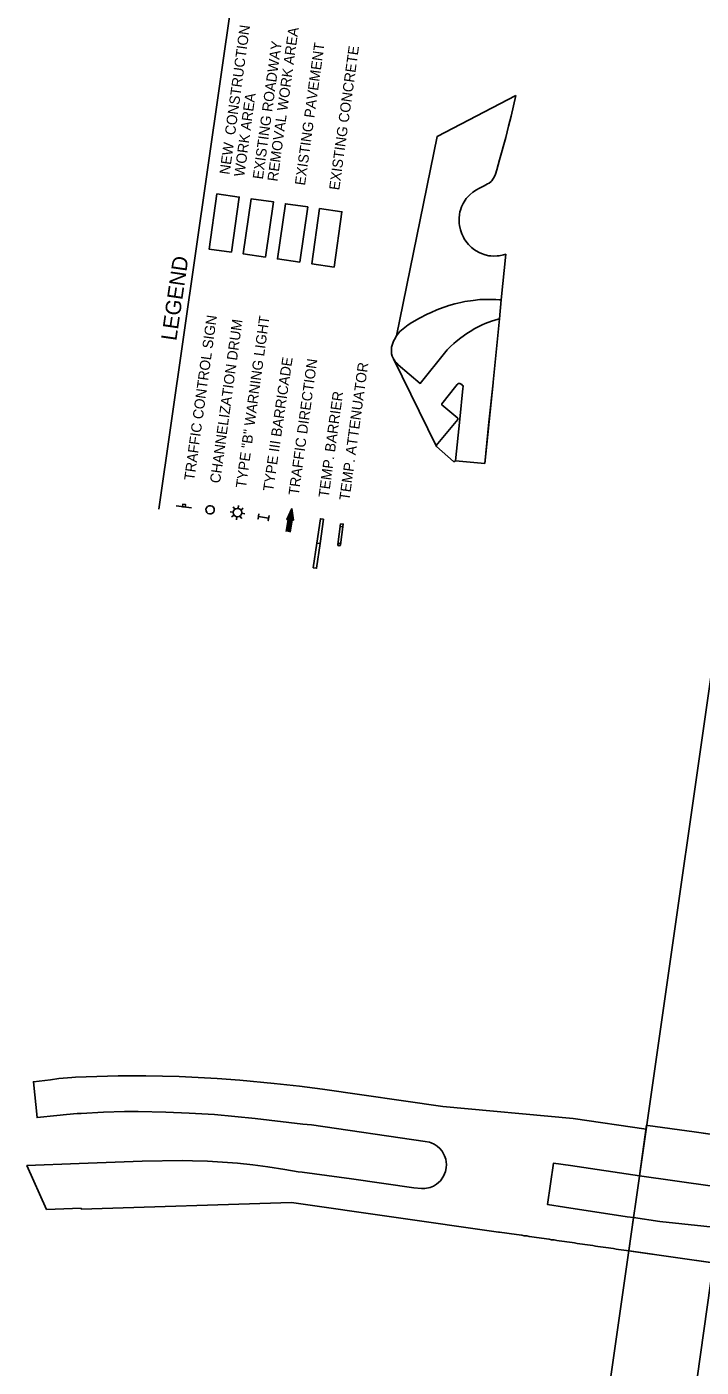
# Model space of a CAD drawing. Extents: x 1795987 to 1799700, y 243690 to 251545.
# Drawn here: x 1797401 to 1797911, y 248808 to 249823 of the extents above; entities that cross this region are included whole.
import ezdxf

# ---------------------------------------------------------------- set-up
doc = ezdxf.new("R2010")
doc.units = 0
for name, color, linetype in [('EP', 7, 'Continuous'), ('LEGEND', 7, 'Continuous'), ('Level 23', 7, 'Continuous'), ('Level 62', 7, 'Continuous')]:
    doc.layers.add(name, color=color, linetype=linetype)

# ---------------------------------------------------------------- blocks, each defined once
blk = doc.blocks.new('T21LR')
at = {"layer": 'Level 23'}
for p, q in [((0, 2), (31.5, 2)), ((0, -2), (31.5, -2))]:
    blk.add_line(p, q, dxfattribs=at)
blk.add_lwpolyline([(0, -2), (4, -2), (4, 2), (0, 2)], close=True, dxfattribs=at)
blk.add_circle((31.5, 0), 2, dxfattribs=at)

msp = doc.modelspace()

# ---------------------------------------------------------------- linework, layer by layer
at = {"layer": 'EP'}
for points in [[(1797729.6, 249614.5), (1797725.1, 249613.4), (1797720.6, 249612.2), (1797718.4, 249611.5), (1797716.1, 249610.7), (1797711.5, 249608.9), (1797707.1, 249606.9), (1797704.1, 249605.5), (1797698.2, 249602.5), (1797692.5, 249599.3), (1797689.7, 249597.6), (1797687.1, 249595.6), (1797685.8, 249594.6), (1797683.5, 249592.4), (1797682.4, 249591.2), (1797680.9, 249589.2), (1797679.3, 249586.5), (1797678.6, 249585.1), (1797677.8, 249582.8), (1797677.2, 249580.6), (1797677.1, 249579.4), (1797677, 249577.7), (1797677.1, 249576.9), (1797677.2, 249575.6), (1797677.7, 249573.7), (1797678.5, 249571.9), (1797679, 249571), (1797680.2, 249569.3), (1797681, 249568.5), (1797682.2, 249567.3), (1797698.9, 249553.1), (1797718.2, 249577.4), (1797719.3, 249578.7), (1797721.7, 249581.2), (1797724.2, 249583.5)], [(1797727.3, 249526.8), (1797715.3, 249536.9), (1797715.1, 249537.8), (1797725.7, 249551.1), (1797726.8, 249552.4), (1797727.3, 249552.8), (1797727.9, 249553), (1797728.2, 249553), (1797728.9, 249553), (1797729.9, 249552.6), (1797730.3, 249552.3), (1797730.9, 249551.7), (1797731, 249551.5), (1797731.2, 249550.8), (1797731.1, 249549.3), (1797728.7, 249526), (1797725.5, 249494.5), (1797724.7, 249494.1), (1797723.9, 249494.1), (1797711.1, 249505.4), (1797711, 249506.2), (1797727.4, 249525.8), (1797727.3, 249526.8)], [(1797950.4, 249280.9), (1797956.6, 249327.5), (1797918.9, 249332.5), (1797841.7, 248792.1)], [(1797841.7, 248792.1), (1797905.8, 248781.8), (1797956.6, 249142)]]:
    msp.add_lwpolyline(points, dxfattribs=at)
at = {"layer": 'LEGEND'}
for p, q in [((1797501.1, 249457.9), (1797556.6, 249845.4)), ((1797525.7, 249458.9), (1797514.1, 249460.5)), ((1797557.3, 249455.7), (1797555.1, 249456)), ((1797556.1, 249452), (1797558, 249453.3)), ((1797558.6, 249457.8), (1797557.2, 249459.7)), ((1797561, 249458.4), (1797561.3, 249460.7)), ((1797563.8, 249450.9), (1797562.4, 249452.7)), ((1797564.9, 249458.6), (1797563.1, 249457.2)), ((1797563.7, 249454.8), (1797566, 249454.5)), ((1797601.6, 249458.4), (1797597.8, 249450.2)), ((1797602.8, 249449.5), (1797601.6, 249458.4)), ((1797560.1, 249452.1), (1797559.7, 249449.8)), ((1797598.8, 249450.1), (1797597.3, 249441.1)), ((1797597.8, 249450.2), (1797598.8, 249450.1)), ((1797600.4, 249440.6), (1797601.8, 249449.6)), ((1797601.8, 249449.6), (1797602.8, 249449.5))]:
    msp.add_line(p, q, dxfattribs=at)
for points in [[(1797555.9, 249652.5), (1797561.9, 249694.3), (1797545, 249696.7), (1797539, 249654.9)], [(1797581.8, 249648.8), (1797587.8, 249690.6), (1797570.9, 249693), (1797564.9, 249651.2)], [(1797607.7, 249645), (1797613.7, 249686.9), (1797596.8, 249689.3), (1797590.8, 249647.5)], [(1797633.6, 249641.3), (1797639.6, 249683.2), (1797622.7, 249685.6), (1797616.7, 249643.8)], [(1797518.9, 249459.8), (1797519.2, 249461.8), (1797521.1, 249461.5), (1797520.8, 249459.5)], [(1797625.7, 249450.4), (1797623.3, 249450.7), (1797620.6, 249432.1), (1797623.1, 249431.8)], [(1797623.1, 249431.8), (1797620.6, 249432.1), (1797617.9, 249413.6), (1797620.4, 249413.2)]]:
    msp.add_lwpolyline(points, close=True, dxfattribs=at)
for points in [[(1797584.5, 249453.1), (1797583.8, 249449.2), (1797584.1, 249451.2), (1797576.4, 249452.4), (1797576.1, 249450.5), (1797576.8, 249454.3)], [(1797599.5, 249453.9), (1797597.5, 249441.1)], [(1797599.9, 249454.7), (1797597.8, 249441.1)], [(1797600.3, 249455.5), (1797598, 249441)], [(1797600.7, 249456.4), (1797598.3, 249441)], [(1797601.1, 249457.2), (1797598.5, 249440.9)], [(1797599.1, 249453), (1797598.7, 249450.1)], [(1797601.5, 249458.1), (1797598.8, 249440.9)], [(1797601.7, 249457.8), (1797599, 249440.9)], [(1797601.8, 249456.9), (1797599.3, 249440.8)], [(1797601.9, 249456), (1797599.6, 249440.8)], [(1797602.1, 249455), (1797599.8, 249440.7)], [(1797602.2, 249454.1), (1797600.1, 249440.7)], [(1797602.3, 249453.2), (1797600.3, 249440.7)], [(1797597.9, 249450.5), (1797597.9, 249450.2)], [(1797598.3, 249451.3), (1797598.1, 249450.2)], [(1797598.7, 249452.2), (1797598.4, 249450.2)], [(1797602.4, 249452.3), (1797602, 249449.6)], [(1797602.5, 249451.3), (1797602.3, 249449.6)], [(1797602.7, 249450.4), (1797602.5, 249449.5)]]:
    msp.add_lwpolyline(points, dxfattribs=at)
msp.add_circle((1797560.5, 249455.3), 3.19, dxfattribs=at)
for start, end in [(81.8439, 261.8439), (261.8439, 81.8439)]:
    msp.add_arc((1797539.8, 249457.4), 3.18, start, end, dxfattribs=at)
at = {"layer": 'Level 62'}
for p, q in [((1797771.3, 249771.3), (1797711.7, 249740.2)), ((1797711.7, 249740.2), (1797680.9, 249589.2)), ((1797760.1, 249616.4), (1797763.5, 249651)), ((1797758.7, 249602), (1797760.1, 249616.4)), ((1797754.1, 249554), (1797758.7, 249602)), ((1797678.5, 249571.9), (1797711.1, 249505.4)), ((1797747.6, 249492.6), (1797754.1, 249553.6)), ((1797754.1, 249553.6), (1797754.1, 249554)), ((1797725.5, 249494.5), (1797747.6, 249492.6))]:
    msp.add_line(p, q, dxfattribs=at)
for points in [[(1797771.3, 249771.3), (1797711.7, 249740.2), (1797680.9, 249589.2), (1797682.4, 249591.2), (1797683.5, 249592.4), (1797685.8, 249594.6), (1797687.1, 249595.6), (1797689.7, 249597.6), (1797692.5, 249599.3), (1797698.2, 249602.5), (1797704.1, 249605.5), (1797707.1, 249606.9), (1797711.5, 249608.9), (1797716.1, 249610.7), (1797718.4, 249611.5), (1797720.6, 249612.2), (1797725.1, 249613.4), (1797729.6, 249614.5), (1797732.7, 249615.1), (1797738.8, 249616), (1797743.9, 249616.6), (1797746.4, 249616.7), (1797750.2, 249616.8), (1797754.1, 249616.7), (1797756, 249616.6), (1797758.7, 249616.4), (1797760.1, 249616.4), (1797763.5, 249651), (1797761.9, 249650.5), (1797758.6, 249649.9), (1797757, 249649.7), (1797754.5, 249649.6), (1797752.3, 249649.7), (1797750.8, 249649.9), (1797747.9, 249650.6), (1797745.2, 249651.5), (1797743.4, 249652.3), (1797741.1, 249653.6), (1797740, 249654.3), (1797737.6, 249656.1), (1797736.6, 249657.1), (1797735.4, 249658.3), (1797733.4, 249660.8), (1797732.2, 249662.6), (1797731.5, 249663.9), (1797730.3, 249666.5), (1797729.2, 249669.5), (1797728.5, 249672.7), (1797728.3, 249674.3), (1797728.2, 249676.7), (1797728.2, 249678.2), (1797728.5, 249681.2), (1797728.9, 249683.1), (1797729.3, 249684.4), (1797730.1, 249686.9), (1797731.3, 249689.5), (1797732.9, 249692), (1797733.7, 249693.2), (1797735.1, 249694.8), (1797736.3, 249696), (1797738.7, 249698), (1797741.4, 249699.8), (1797743.3, 249700.9), (1797747.2, 249702.9), (1797749.7, 249704.2), (1797751, 249704.9), (1797752.4, 249706.1), (1797753, 249706.7), (1797753.9, 249707.8), (1797754.4, 249708.5), (1797755.1, 249710), (1797755.7, 249711.6), (1797756.7, 249714.9), (1797758.9, 249722.6), (1797763.5, 249739.5), (1797765.7, 249747.9), (1797767.7, 249755.7), (1797771.3, 249771.3)], [(1797763.5, 249651), (1797761.9, 249650.5), (1797758.6, 249649.9), (1797757, 249649.7), (1797754.5, 249649.6), (1797752.3, 249649.7), (1797750.8, 249649.9), (1797747.9, 249650.6), (1797745.2, 249651.5), (1797743.4, 249652.3), (1797741.1, 249653.6), (1797740, 249654.3), (1797737.6, 249656.1), (1797736.6, 249657.1), (1797735.4, 249658.3), (1797733.4, 249660.8), (1797732.2, 249662.6), (1797731.5, 249663.9), (1797730.3, 249666.5), (1797729.2, 249669.5), (1797728.5, 249672.7), (1797728.3, 249674.3), (1797728.2, 249676.7), (1797728.2, 249678.2), (1797728.5, 249681.2), (1797728.9, 249683.1), (1797729.3, 249684.4), (1797730.1, 249686.9), (1797731.3, 249689.5), (1797732.9, 249692), (1797733.7, 249693.2), (1797735.1, 249694.8), (1797736.3, 249696), (1797738.7, 249698), (1797741.4, 249699.8), (1797743.3, 249700.9), (1797747.2, 249702.9), (1797749.7, 249704.2), (1797751, 249704.9), (1797752.4, 249706.1), (1797753, 249706.7), (1797753.9, 249707.8), (1797754.4, 249708.5), (1797755.1, 249710), (1797755.7, 249711.6), (1797756.7, 249714.9), (1797758.9, 249722.6), (1797763.5, 249739.5), (1797765.7, 249747.9), (1797767.7, 249755.7), (1797771.3, 249771.3)], [(1797590.8, 249647.5), (1797607.7, 249645), (1797613.7, 249686.9), (1797596.8, 249689.3), (1797590.8, 249647.5)], [(1797760.1, 249616.4), (1797758.7, 249616.4), (1797756, 249616.6), (1797754.1, 249616.7), (1797750.2, 249616.8), (1797746.4, 249616.7), (1797743.9, 249616.6), (1797738.8, 249616), (1797732.7, 249615.1), (1797729.6, 249614.5), (1797725.1, 249613.4), (1797720.6, 249612.2), (1797718.4, 249611.5), (1797716.1, 249610.7), (1797711.5, 249608.9), (1797707.1, 249606.9), (1797704.1, 249605.5), (1797698.2, 249602.5), (1797692.5, 249599.3), (1797689.7, 249597.6), (1797687.1, 249595.6), (1797685.8, 249594.6), (1797683.5, 249592.4), (1797682.4, 249591.2), (1797680.9, 249589.2)], [(1797758.7, 249602), (1797757.7, 249601.8), (1797752.7, 249600.3), (1797747.9, 249598.5), (1797745.6, 249597.5), (1797743.7, 249596.6), (1797740.1, 249594.7), (1797736.5, 249592.5), (1797734.2, 249591), (1797729.6, 249587.8), (1797726, 249585), (1797724.2, 249583.5), (1797721.7, 249581.2), (1797719.3, 249578.7), (1797718.2, 249577.4), (1797698.9, 249553.1), (1797682.2, 249567.3), (1797681, 249568.5), (1797680.2, 249569.3), (1797679, 249571), (1797678.5, 249571.9)], [(1797727.3, 249526.8), (1797715.3, 249536.9), (1797715.1, 249537.8), (1797725.7, 249551.1), (1797726.8, 249552.4), (1797727.3, 249552.8), (1797727.9, 249553), (1797728.2, 249553), (1797728.9, 249553), (1797729.9, 249552.6), (1797730.3, 249552.3), (1797730.9, 249551.7), (1797731, 249551.5), (1797731.2, 249550.8), (1797731.1, 249549.3), (1797728.7, 249526), (1797725.5, 249494.5)], [(1797747.6, 249492.6), (1797750.8, 249523.7), (1797754.1, 249553.6)], [(1797711.1, 249505.4), (1797711, 249506.2), (1797727.4, 249525.8), (1797727.3, 249526.8)], [(1797442.3, 248928.4), (1797442.3, 248927.8), (1797601.3, 248932.8), (1797758, 248910.4), (1797758.8, 248910.3), (1797760.6, 248910.1), (1797762.5, 248909.8), (1797764.3, 248909.5), (1797766.2, 248909.3), (1797768, 248909), (1797769.9, 248908.7), (1797771.8, 248908.5), (1797773.7, 248908.2), (1797775.6, 248907.9), (1797777.5, 248907.6), (1797779.4, 248907.4), (1797781.3, 248907.1), (1797783.2, 248906.8), (1797785.1, 248906.6), (1797786.9, 248906.3), (1797788.8, 248906), (1797790.7, 248905.7), (1797792.6, 248905.5), (1797794.5, 248905.2), (1797796.4, 248904.9), (1797798.3, 248904.6), (1797800.2, 248904.4), (1797802.1, 248904.1), (1797804, 248903.8), (1797805.9, 248903.5), (1797807.9, 248903.2), (1797809.8, 248903), (1797811.8, 248902.7), (1797813.7, 248902.4), (1797815.7, 248902.1), (1797817.7, 248901.8), (1797819.6, 248901.5), (1797821.6, 248901.2), (1797823.5, 248901), (1797825.5, 248900.7), (1797827.4, 248900.4), (1797829.4, 248900.1), (1797831.4, 248899.8), (1797833.3, 248899.5), (1797835.3, 248899.2), (1797837.2, 248899), (1797839.2, 248898.7), (1797841.2, 248898.4), (1797843.1, 248898.1), (1797845.1, 248897.8), (1797847, 248897.5), (1797849, 248897.2), (1797850.9, 248897), (1797852.9, 248896.7), (1797854.9, 248896.4), (1797856.6, 248896.1), (1797860.2, 248921.3), (1797855.5, 248922), (1797808, 248929.2), (1797795.2, 248931.2), (1797799.8, 248962.6), (1797812.5, 248960.7), (1797864.7, 248953), (1797869.7, 248988.3), (1797814.6, 248996.3), (1797716, 249005.4), (1797624.8, 249018.5), (1797607.5, 249020.8), (1797588.4, 249023), (1797562.3, 249025.4), (1797545.1, 249026.7), (1797516.4, 249028.1), (1797491.2, 249028.6), (1797470.2, 249028.6), (1797438, 249027.7), (1797435.2, 249027.5), (1797425.4, 249026.6), (1797418.9, 249025.8), (1797406.1, 249024.2), (1797408.8, 248997.1), (1797423.7, 248998.7), (1797431.2, 248999.4), (1797439.2, 249000.1), (1797442.3, 249000.3), (1797459.1, 249001.2), (1797474.9, 249001.6), (1797485.4, 249001.7), (1797506.4, 249001.3), (1797523.9, 249000.5), (1797543.2, 248999.3), (1797573.8, 248996.5), (1797609.9, 248992.2), (1797616.5, 248991.6), (1797702.5, 248979), (1797705.8, 248978.4), (1797707.1, 248978), (1797709.5, 248976.9), (1797711.7, 248975.4), (1797713.7, 248973.7), (1797715.4, 248971.6), (1797717.3, 248968.1), (1797718.2, 248965.6), (1797718.7, 248961.6), (1797718.5, 248959), (1797718, 248956.3), (1797716.4, 248952.6), (1797714.1, 248949.3), (1797711.1, 248946.6), (1797708.8, 248945.2), (1797706.3, 248944.2), (1797702.4, 248943.4), (1797699.7, 248943.3), (1797694.1, 248944), (1797646.8, 248950.7), (1797609.4, 248955.7), (1797606.5, 248955.9), (1797596.3, 248957.7), (1797583.6, 248959.8), (1797572.1, 248961.3), (1797560.6, 248962.5), (1797549.2, 248963.4), (1797537.9, 248964), (1797526.6, 248964.4), (1797519, 248964.5), (1797488.4, 248964.1), (1797440.8, 248962.3), (1797401.1, 248960.7), (1797416.1, 248927.5), (1797442.3, 248928.4)], [(1797864.7, 248953), (1797870.2, 248991.3), (1797871.2, 248991.1), (1797906.1, 248986.4), (1797934.1, 248982.3)], [(1797939, 248981.6), (1797906.1, 248986.4), (1797871.2, 248991.1)], [(1797975.3, 248937.3), (1797864.7, 248953)], [(1797994.6, 248906.7), (1797992, 248906.6), (1797880.1, 248918.3), (1797860.2, 248921.3), (1797856.6, 248896.1), (1797856.8, 248896.1), (1797858.3, 248895.9), (1797858.8, 248895.8), (1797858.8, 248895.8), (1797892.1, 248891.1), (1797920.6, 248887)], [(1797858.3, 248895.9), (1797892.1, 248891.1), (1797925.5, 248886.3)]]:
    msp.add_lwpolyline(points, dxfattribs=at)

# ---------------------------------------------------------------- block references
at = {"layer": 'LEGEND', "xscale": 0.5000000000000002, "yscale": 0.5000000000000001, "rotation": -98.00678026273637}
msp.add_blockref('T21LR', (1797639.6, 249446.7), dxfattribs=at)

# ---------------------------------------------------------------- texts
at = {"layer": 'LEGEND'}
for s, height, rotation, p in [('NEW  CONSTRUCTION', 7.8, 82.1569, (1797554.5, 249711)), ('REMOVAL WORK AREA', 7.8, 82.1569, (1797590.8, 249705.8)), ('EXISTING ROADWAY', 7.8, 82.1569, (1797579.7, 249707.4)), ('EXISTING PAVEMENT', 7.8, 82.1569, (1797611.6, 249702.8)), ('EXISTING CONCRETE', 7.8, 82.1569, (1797637.5, 249699.2)), ('WORK AREA', 7.8, 82.1569, (1797565.6, 249709.4)), ('LEGEND', 11.7, 81.6779, (1797514.2, 249585)), ('TRAFFIC CONTROL SIGN', 7.8, 82.1569, (1797527.8, 249479.2)), ('CHANNELIZATION DRUM', 7.8, 82.1569, (1797547.3, 249477.2)), ('TYPE "B" WARNING LIGHT', 7.8, 82.1569, (1797566.9, 249473.6)), ('TYPE III BARRICADE', 7.8, 81.6779, (1797587.5, 249471)), ('TRAFFIC DIRECTION', 7.8, 82.1569, (1797606.8, 249468)), ('TEMP. ATTENUATOR', 7.8, 82.1569, (1797645.2, 249464.1)), ('TEMP. BARRIER', 7.8, 82.1569, (1797629.5, 249466.3))]:
    msp.add_text(s, height=height, rotation=rotation, dxfattribs=at).set_placement(p)

doc.saveas('drawing.dxf')
